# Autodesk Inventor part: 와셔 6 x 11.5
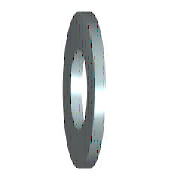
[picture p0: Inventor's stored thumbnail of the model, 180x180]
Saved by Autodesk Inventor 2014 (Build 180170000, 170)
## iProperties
IsCustomPart: 1
Created: 2012-02
Part Number: 와셔 6 x 11.5
Material: 강철, 연강
Description: 평면 와셔
Document SubType Name: Modeling
Standard: KS B 1326
Designer: mduedu
Standards Organization: KS
Language: ko-KR
Size Designation: 6x11.5
Categories: <MemberInstance><Categories><Category DisplayName="조임쇠" InternalName="e4da775c-781d-43d5-af7c-5136215cf5a6" Mnemonic="FSTN"><Category DisplayName="와셔" InternalN
Density: 7.86 g/cm^3
Mass: 0.901687 g
Surface Area: 2.33373 cm^2
Volume: 0.114718 cm^3
Appearance: 주황색
Author: mduedu
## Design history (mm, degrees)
sketch "스케치"
  geometry: C1 r 5.75 at (0, 0); C2 r 3.2 at (0, 0); 1 further point
  constraints: 2 centre point, 2 coincident
  dimensions: "d0" = 6.4 diameter of C2 (= SD1); "d1" = 11.5 diameter of C1 (= SD2)
extrude "본체" new body sketch "스케치" distance "d2" = 1.6 (= SD); taper "d3" = 0 deg
workaxis "Work Axis1"
workplane "Work Plane1"
body "Solid1"
other parameters: "SD1" = 6.4 [user parameter; used in 1 equation term], "SD2" = 11.5 [user parameter; used in 1 equation term], "SD" = 1.6 [user parameter; used in 1 equation term], "d4" = 0, "d5" = 0, "d6" = 0, "d7" = 0, "NND" = 6 [user parameter]
